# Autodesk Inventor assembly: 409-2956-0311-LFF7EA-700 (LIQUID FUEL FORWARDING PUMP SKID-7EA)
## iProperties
Created: 2010-06
Part Number: 409-2956-0311-LFF7EA-700 (LIQUID FUEL FORWARDING PUMP SKID-7EA)
Document SubType Name: Assembly
Designer: S. Boerckel
Mass: 2.65421e+06 g
Surface Area: 750857 cm^2
Volume: 395615 cm^3
Density: 6.70908 g/cm^3
Description: MECHANICAL
Material: ASSEMBLY
Author: S. Boerckel
Revision Number: B
Title: MECHANICAL
Subject: LIQUID FUEL FORWARDING PUMP SKID-7EA
